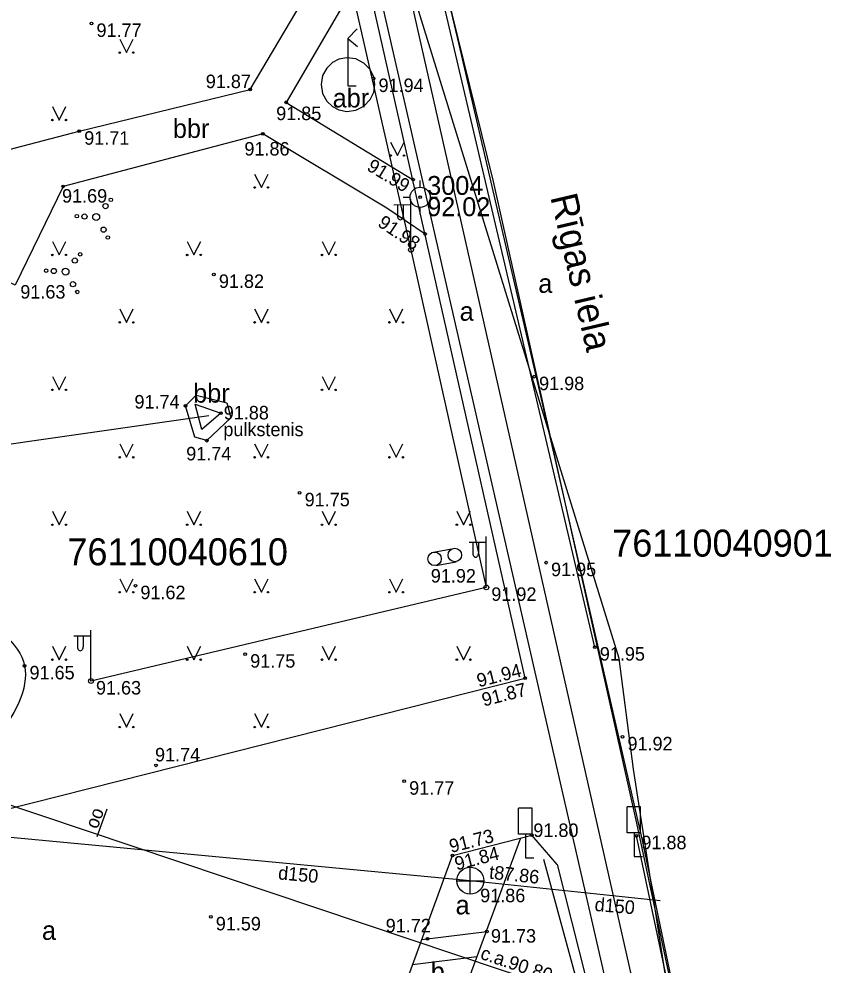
# Model space of a CAD drawing. Extents: x 634272 to 634544, y 247463 to 247653.
# Drawn here: x 634443.51 to 634473.63, y 247553.68 to 247588.75 of the extents above; entities that cross this region are included whole.
import ezdxf

# ---------------------------------------------------------------- set-up
doc = ezdxf.new("R2010")
doc.units = 0
for name, color, linetype in [('APGR_SARK_####_####_#', 7, 'Continuous'), ('APGS_ELEM_####_####_#', 7, 'Continuous'), ('APGS_VADP_ZSPR_####_#', 7, 'Continuous'), ('BUVE_BDET_####_####_#', 7, 'Continuous'), ('BUVE_BDET_####_TKST_#', 7, 'Continuous'), ('BUVE_ELEM_####_####_#', 7, 'Continuous'), ('CELI_CAPM_####_####_#', 7, 'Continuous'), ('CELI_CMAL_####_####_#', 7, 'Continuous'), ('CELI_CSEG_####_TKST_#', 7, 'Continuous'), ('CELI_ELEM_####_####_#', 7, 'Continuous'), ('CELI_IELA_####_TKST_#', 7, 'Continuous'), ('CELI_KAPN_####_####_#', 7, 'Continuous'), ('CELI_SEGL_####_####_#', 7, 'Continuous'), ('CELI_ZIME_####_####_#', 7, 'Continuous'), ('GEOD_ELEM_####_####_#', 7, 'Continuous'), ('GEOD_ELEM_####_TKST_#', 7, 'Continuous'), ('NORB_ZOGS_ZMET_####_#', 7, 'Continuous'), ('RAMI_UZMR_####_####_#', 7, 'Continuous'), ('RELJ_AATZ_####_TKST_#', 7, 'Continuous'), ('RELJ_ELEM_####_####_#', 7, 'Continuous'), ('ROBZ_KADS_####_TKST_#', 7, 'Continuous'), ('ROBZ_PROJ_####_####_#', 7, 'Continuous'), ('SAKK_IZVK_####_TKST_#', 7, 'Continuous'), ('SAKK_KKAN_####_####_#', 7, 'Continuous'), ('SAKK_KKAN_####_TKST_#', 7, 'Continuous'), ('SKAN_ELEM_####_####_#', 7, 'Continuous'), ('SKAN_ELEM_PAST_TKST_#', 7, 'Continuous'), ('SKAN_VADP_PAST_####_#', 7, 'Continuous'), ('SKAN_VADP_PAST_TKST_#', 7, 'Continuous'), ('TERT_DZOG_####_####_#', 7, 'Continuous'), ('TERT_ELEM_####_####_#', 7, 'Continuous'), ('TERT_KONT_####_####_#', 7, 'Continuous')]:
    doc.layers.add(name, color=color, linetype=linetype)

msp = doc.modelspace()

# ---------------------------------------------------------------- linework, layer by layer
at = {"layer": 'APGR_SARK_####_####_#'}
msp.add_line((634472.239, 247522.641), (634452.431, 247609.249), dxfattribs=at)
at = {"layer": 'APGS_ELEM_####_####_#'}
for p, q in [((634458.049, 247580.186), (634458.049, 247582.069)), ((634458.049, 247581.853), (634457.414, 247581.848)), ((634457.549, 247581.849), (634457.549, 247581.457)), ((634457.759, 247581.851), (634457.759, 247581.457)), ((634460.842, 247567.679), (634460.842, 247569.562)), ((634460.842, 247569.346), (634460.207, 247569.341)), ((634460.342, 247569.342), (634460.342, 247568.95)), ((634460.552, 247569.344), (634460.552, 247568.95)), ((634446.181, 247564.209), (634446.181, 247566.092)), ((634446.181, 247565.876), (634445.546, 247565.871)), ((634445.681, 247565.872), (634445.681, 247565.48)), ((634445.891, 247565.874), (634445.891, 247565.48))]:
    msp.add_line(p, q, dxfattribs=at)
for centre in [(634458.049, 247580.186), (634460.842, 247567.679), (634446.181, 247564.209)]:
    msp.add_circle(centre, 0.09, dxfattribs=at)
for centre in [(634457.654, 247581.457), (634460.447, 247568.95), (634445.786, 247565.48)]:
    msp.add_ellipse(centre, major_axis=(0, 0.151), ratio=0.695971, start_param=1.570796, end_param=4.712389, dxfattribs=at)
at = {"layer": 'APGS_VADP_ZSPR_####_#'}
for points in [[(634424.64, 247564.493), (634427.489, 247567.387), (634428.243, 247568.282), (634428.556, 247569.174), (634428.62, 247569.734), (634428.349, 247570.951), (634427.518, 247573.97), (634425.055, 247583.293), (634424.177, 247586.368), (634423.255, 247589.552), (634422.487, 247592.599), (634438.755, 247598.02), (634453.341, 247601.325), (634455.217, 247592.645), (634458.049, 247580.186), (634460.842, 247567.679), (634446.181, 247564.209)], [(634425.999, 247571.336), (634432.246, 247571.428), (634450.555, 247574.05)]]:
    msp.add_lwpolyline(points, dxfattribs=at)
at = {"layer": 'BUVE_BDET_####_####_#'}
msp.add_lwpolyline([(634450.297, 247573.534), (634450.05, 247574.469), (634451.002, 247574.132), (634450.297, 247573.534)], dxfattribs=at)
at = {"layer": 'BUVE_ELEM_####_####_#'}
for centre in [(634459.675, 247568.878), (634458.924, 247568.738)]:
    msp.add_circle(centre, 0.25, dxfattribs=at)
at = {"layer": 'CELI_CAPM_####_####_#'}
for points in [[(634462.278, 247564.311), (634455.906, 247592.579), (634453.174, 247605.031)], [(634386.18, 247584.245), (634386.517, 247583.098), (634389.042, 247573.196), (634391.897, 247562.219), (634393.7, 247555.164), (634394.221, 247554.237), (634394.857, 247553.225), (634395.836, 247552.623), (634399.496, 247551.073), (634400.928, 247550.806), (634417.097, 247555.253), (634426.457, 247557.809), (634427.052, 247555.379), (634437.491, 247558.047), (634462.278, 247564.311)], [(634457.574, 247552.223), (634459.589, 247557.74), (634462.532, 247558.496)], [(634463.467, 247557.413), (634465.341, 247550.039), (634461.38, 247548.991), (634462.172, 247545.409), (634466.133, 247546.478), (634469.47, 247530.921)]]:
    msp.add_lwpolyline(points, dxfattribs=at)
at = {"layer": 'CELI_CMAL_####_####_#'}
for points in [[(634472.031, 247532.571), (634469.381, 247545.11), (634466.419, 247558.939), (634461.107, 247582.724), (634454.551, 247609.343)], [(634454.416, 247599.108), (634444.542, 247596.807), (634437.329, 247582.391), (634445.746, 247584.585), (634452.082, 247586.129), (634455.906, 247592.579)], [(634456.349, 247590.673), (634453.418, 247585.656), (634458.133, 247582.79)], [(634456.705, 247586.313), (634456.666, 247586.587), (634456.535, 247586.869), (634456.303, 247587.111), (634455.998, 247587.265), (634455.672, 247587.306), (634455.377, 247587.25), (634455.138, 247587.127), (634454.929, 247586.928), (634454.773, 247586.647), (634454.715, 247586.313), (634454.773, 247585.978), (634454.929, 247585.697), (634455.138, 247585.499), (634455.377, 247585.376), (634455.672, 247585.319), (634455.998, 247585.361), (634456.303, 247585.514), (634456.535, 247585.757), (634456.666, 247586.039), (634456.705, 247586.313)], [(634458.572, 247580.776), (634457.15, 247581.734), (634452.558, 247584.487), (634445.153, 247582.542), (634443.376, 247578.883), (634438.996, 247580.966), (634436.253, 247580.228), (634434.43, 247576.565)], [(634449.685, 247574.411), (634450.077, 247574.803), (634451.226, 247574.515), (634451.364, 247573.967), (634450.48, 247573.117), (634450.028, 247573.252), (634449.685, 247574.411)], [(634460.04, 247552.762), (634462.126, 247558.392)], [(634463.467, 247557.413), (634462.532, 247558.496)]]:
    msp.add_lwpolyline(points, dxfattribs=at)
at = {"layer": 'CELI_ELEM_####_####_#'}
for p, q in [((634462.538, 247559.497), (634462.038, 247559.497)), ((634462.038, 247558.528), (634462.038, 247559.497)), ((634462.538, 247558.528), (634462.538, 247559.497)), ((634466.566, 247559.551), (634466.066, 247559.551)), ((634466.066, 247558.582), (634466.066, 247559.551)), ((634466.566, 247558.582), (634466.566, 247559.551)), ((634466.566, 247558.582), (634466.066, 247558.582)), ((634466.32, 247558.582), (634466.32, 247557.704)), ((634462.538, 247558.528), (634462.038, 247558.528)), ((634462.292, 247558.528), (634462.292, 247557.65)), ((634462.292, 247557.65), (634462.607, 247557.65)), ((634466.32, 247557.704), (634466.635, 247557.704))]:
    msp.add_line(p, q, dxfattribs=at)
for points in [[(634456.053, 247588.379), (634455.711, 247588.023), (634456.067, 247587.724)], [(634455.711, 247588.023), (634455.711, 247586.271), (634456.01, 247586.271)]]:
    msp.add_lwpolyline(points, dxfattribs=at)
at = {"layer": 'CELI_KAPN_####_####_#'}
msp.add_line((634460.495, 247553.99), (634458.111, 247553.692), dxfattribs=at)
at = {"layer": 'CELI_SEGL_####_####_#'}
msp.add_lwpolyline([(634458.452, 247554.627), (634460.864, 247554.929)], dxfattribs=at)
at = {"layer": 'CELI_ZIME_####_####_#'}
for p, q in [((634458.878, 247568.984), (634459.629, 247569.124)), ((634458.97, 247568.492), (634459.721, 247568.632))]:
    msp.add_line(p, q, dxfattribs=at)
at = {"layer": 'GEOD_ELEM_####_####_#'}
for p, q in [((634458.39, 247582.512), (634458.39, 247582.762)), ((634457.765, 247582.137), (634458.015, 247582.137)), ((634458.765, 247582.137), (634459.015, 247582.137)), ((634458.39, 247581.512), (634458.39, 247581.762))]:
    msp.add_line(p, q, dxfattribs=at)
for radius in [0.375, 0.05]:
    msp.add_circle((634458.39, 247582.137), radius, dxfattribs=at)
at = {"layer": 'NORB_ZOGS_ZMET_####_#'}
for points in [[(634464.866, 247565.466), (634454.698, 247608.782)], [(634471.548, 247534.262), (634466.407, 247558.475)]]:
    msp.add_lwpolyline(points, dxfattribs=at)
at = {"layer": 'RAMI_UZMR_####_####_#'}
msp.add_lwpolyline([(634357.63, 247590.775), (634379.264, 247596.642), (634392.424, 247602.216), (634402.994, 247605.715), (634421.735, 247609.504), (634423.082, 247609.702), (634425.783, 247608.304), (634427.755, 247600.855), (634433.048, 247602.581), (634454.806, 247608.92), (634459.819, 247587.798), (634462.766, 247575.147), (634466.614, 247558.36), (634469.076, 247546.545)], dxfattribs=at)
at = {"layer": 'RELJ_ELEM_####_####_#'}
for centre in [(634446.201, 247588.58), (634456.66, 247586.538), (634452.082, 247586.129), (634453.418, 247585.656), (634445.746, 247584.585), (634452.558, 247584.487), (634458.133, 247582.79), (634445.153, 247582.542), (634458.393, 247582.141), (634458.572, 247580.776), (634450.74, 247579.278), (634462.614, 247575.489), (634449.685, 247574.411), (634451.002, 247574.132), (634450.48, 247573.117), (634453.92, 247571.184), (634463.057, 247568.595), (634447.829, 247567.742), (634451.901, 247565.204), (634464.866, 247565.466), (634443.717, 247564.77), (634462.278, 247564.311), (634465.891, 247562.138), (634448.593, 247561.083), (634457.796, 247560.496), (634462.532, 247558.496), (634466.407, 247558.475), (634459.589, 247557.74), (634450.624, 247555.467), (634458.657, 247554.653), (634460.864, 247554.929)]:
    msp.add_circle(centre, 0.05, dxfattribs=at)
at = {"layer": 'ROBZ_PROJ_####_####_#'}
for points in [[(634465.768, 247565.048), (634453.433, 247604.869)], [(634466.305, 247560.948), (634465.768, 247565.048)], [(634472.285, 247522.369), (634466.305, 247560.948)]]:
    msp.add_lwpolyline(points, dxfattribs=at)
at = {"layer": 'SAKK_IZVK_####_TKST_#'}
msp.add_line((634446.414, 247558.452), (634446.786, 247559.47), dxfattribs=at)
at = {"layer": 'SAKK_KKAN_####_####_#'}
for points in [[(634452.888, 247611.435), (634454.857, 247603.576), (634466.565, 247551.758), (634472.201, 247519.993)], [(634466.565, 247551.758), (634428.878, 247564.406)]]:
    msp.add_lwpolyline(points, dxfattribs=at)
at = {"layer": 'SKAN_ELEM_####_####_#'}
for p, q in [((634460.247, 247556.307), (634460.247, 247557.307)), ((634459.747, 247556.807), (634460.747, 247556.807))]:
    msp.add_line(p, q, dxfattribs=at)
msp.add_circle((634460.247, 247556.807), 0.5, dxfattribs=at)
at = {"layer": 'SKAN_VADP_PAST_####_#'}
msp.add_lwpolyline([(634467.293, 247556.065), (634460.247, 247556.807), (634435.579, 247559.128), (634432.448, 247572.232), (634426.846, 247593.259), (634423.583, 247606.965), (634413.214, 247604.726), (634403.305, 247602.476), (634405.576, 247593.489), (634409.131, 247581.899)], dxfattribs=at)
at = {"layer": 'TERT_DZOG_####_####_#'}
msp.add_lwpolyline([(634464.963, 247550.289), (634462.971, 247557.593)], dxfattribs=at)
at = {"layer": 'TERT_ELEM_####_####_#'}
for p, q in [((634447.25, 247588), (634447.5, 247587.5)), ((634447.5, 247587.5), (634447.75, 247588)), ((634444.75, 247585.5), (634445, 247585)), ((634445, 247585), (634445.25, 247585.5)), ((634457.294, 247584.185), (634457.544, 247583.685)), ((634457.544, 247583.685), (634457.794, 247584.185)), ((634452.25, 247583), (634452.5, 247582.5)), ((634452.5, 247582.5), (634452.75, 247583)), ((634444.75, 247580.5), (634445, 247580)), ((634445, 247580), (634445.25, 247580.5)), ((634449.75, 247580.5), (634450, 247580)), ((634450, 247580), (634450.25, 247580.5)), ((634454.75, 247580.5), (634455, 247580)), ((634455, 247580), (634455.25, 247580.5)), ((634447.25, 247578), (634447.5, 247577.5)), ((634447.5, 247577.5), (634447.75, 247578)), ((634452.25, 247578), (634452.5, 247577.5)), ((634452.5, 247577.5), (634452.75, 247578)), ((634457.25, 247578), (634457.5, 247577.5)), ((634457.5, 247577.5), (634457.75, 247578)), ((634444.75, 247575.5), (634445, 247575)), ((634445, 247575), (634445.25, 247575.5)), ((634454.75, 247575.5), (634455, 247575)), ((634455, 247575), (634455.25, 247575.5)), ((634447.25, 247573), (634447.5, 247572.5)), ((634447.5, 247572.5), (634447.75, 247573)), ((634452.25, 247573), (634452.5, 247572.5)), ((634452.5, 247572.5), (634452.75, 247573)), ((634457.25, 247573), (634457.5, 247572.5)), ((634457.5, 247572.5), (634457.75, 247573)), ((634444.75, 247570.5), (634445, 247570)), ((634445, 247570), (634445.25, 247570.5)), ((634449.75, 247570.5), (634450, 247570)), ((634450, 247570), (634450.25, 247570.5)), ((634454.75, 247570.5), (634455, 247570)), ((634455, 247570), (634455.25, 247570.5)), ((634459.75, 247570.5), (634460, 247570)), ((634460, 247570), (634460.25, 247570.5)), ((634447.25, 247568), (634447.5, 247567.5)), ((634447.5, 247567.5), (634447.75, 247568)), ((634452.25, 247568), (634452.5, 247567.5)), ((634452.5, 247567.5), (634452.75, 247568)), ((634457.25, 247568), (634457.5, 247567.5)), ((634457.5, 247567.5), (634457.75, 247568)), ((634444.75, 247565.5), (634445, 247565)), ((634445, 247565), (634445.25, 247565.5)), ((634449.75, 247565.5), (634450, 247565)), ((634450, 247565), (634450.25, 247565.5)), ((634454.75, 247565.5), (634455, 247565)), ((634455, 247565), (634455.25, 247565.5)), ((634459.75, 247565.5), (634460, 247565)), ((634460, 247565), (634460.25, 247565.5)), ((634447.25, 247563), (634447.5, 247562.5)), ((634447.5, 247562.5), (634447.75, 247563)), ((634452.25, 247563), (634452.5, 247562.5)), ((634452.5, 247562.5), (634452.75, 247563))]:
    msp.add_line(p, q, dxfattribs=at)
for centre, radius in [((634447.25, 247587.5), 0.028), ((634447.75, 247587.5), 0.0263), ((634444.75, 247585), 0.028), ((634445.25, 247585), 0.0263), ((634457.293, 247583.685), 0.028), ((634457.793, 247583.685), 0.0263), ((634452.25, 247582.5), 0.028), ((634452.75, 247582.5), 0.0263), ((634446.918, 247582.042), 0.064), ((634446.722, 247581.811), 0.096), ((634445.656, 247581.437), 0.064), ((634445.94, 247581.424), 0.096), ((634446.374, 247581.403), 0.128), ((634446.65, 247580.936), 0.096), ((634446.808, 247580.647), 0.064), ((634444.75, 247580), 0.028), ((634445.25, 247580), 0.0263), ((634445.782, 247580.022), 0.064), ((634449.75, 247580), 0.028), ((634450.25, 247580), 0.0263), ((634454.75, 247580), 0.028), ((634455.25, 247580), 0.0263), ((634445.586, 247579.791), 0.096), ((634444.52, 247579.417), 0.064), ((634444.804, 247579.404), 0.096), ((634445.238, 247579.383), 0.128), ((634445.514, 247578.916), 0.096), ((634445.672, 247578.627), 0.064), ((634447.25, 247577.5), 0.028), ((634447.75, 247577.5), 0.0263), ((634452.25, 247577.5), 0.028), ((634452.75, 247577.5), 0.0263), ((634457.25, 247577.5), 0.028), ((634457.75, 247577.5), 0.0263), ((634444.75, 247575), 0.028), ((634445.25, 247575), 0.0263), ((634454.75, 247575), 0.028), ((634455.25, 247575), 0.0263), ((634447.25, 247572.5), 0.028), ((634447.75, 247572.5), 0.0263), ((634452.25, 247572.5), 0.028), ((634452.75, 247572.5), 0.0263), ((634457.25, 247572.5), 0.028), ((634457.75, 247572.5), 0.0263), ((634444.75, 247570), 0.028), ((634445.25, 247570), 0.0263), ((634449.75, 247570), 0.028), ((634450.25, 247570), 0.0263), ((634454.75, 247570), 0.028), ((634455.25, 247570), 0.0263), ((634459.75, 247570), 0.028), ((634460.25, 247570), 0.0263), ((634447.25, 247567.5), 0.028), ((634447.75, 247567.5), 0.0263), ((634452.25, 247567.5), 0.028), ((634452.75, 247567.5), 0.0263), ((634457.25, 247567.5), 0.028), ((634457.75, 247567.5), 0.0263), ((634444.75, 247565), 0.028), ((634445.25, 247565), 0.0263), ((634449.75, 247565), 0.028), ((634450.25, 247565), 0.0263), ((634454.75, 247565), 0.028), ((634455.25, 247565), 0.0263), ((634459.75, 247565), 0.028), ((634460.25, 247565), 0.0263), ((634447.25, 247562.5), 0.028), ((634447.75, 247562.5), 0.0263), ((634452.25, 247562.5), 0.028), ((634452.75, 247562.5), 0.0263)]:
    msp.add_circle(centre, radius, dxfattribs=at)
at = {"layer": 'TERT_KONT_####_####_#'}
msp.add_spline([(634436.545, 247568.569), (634443.717, 247564.77), (634439.253, 247558.492)], degree=3, dxfattribs=at)

# ---------------------------------------------------------------- texts
at = {"layer": 'BUVE_BDET_####_TKST_#'}
msp.add_text('pulkstenis', height=0.5, dxfattribs=at).set_placement((634451.091, 247573.284))
at = {"layer": 'CELI_CSEG_####_TKST_#'}
for s, p in [('abr', (634455.146, 247585.467)), ('bbr', (634449.22, 247584.337)), ('a', (634462.771, 247578.596)), ('a', (634459.855, 247577.562)), ('bbr', (634449.972, 247574.526)), ('a', (634459.703, 247555.56)), ('a', (634444.365, 247554.615)), ('b', (634458.783, 247553.087))]:
    msp.add_text(s, height=0.7, dxfattribs=at).set_placement(p)
at = {"layer": 'CELI_IELA_####_TKST_#'}
msp.add_text('Rīgas iela', height=1, rotation=283.2104, dxfattribs=at).set_placement((634463.21, 247582.152))
at = {"layer": 'GEOD_ELEM_####_TKST_#'}
for s, p in [(' 3004', (634458.39, 247582.226)), (' 92.02', (634458.39, 247581.437))]:
    msp.add_text(s, height=0.7, dxfattribs=at).set_placement(p)
at = {"layer": 'RELJ_AATZ_####_TKST_#'}
for s, p in [(' 91.77', (634446.201, 247588.08)), (' 91.87', (634450.254, 247586.183)), (' 91.94', (634456.66, 247586.038)), (' 91.85', (634452.865, 247584.997)), (' 91.71', (634445.746, 247584.085)), (' 91.86', (634451.686, 247583.685)), (' 91.69', (634444.923, 247581.94)), (' 91.82', (634450.74, 247578.778)), (' 91.63', (634443.376, 247578.383)), (' 91.98', (634462.614, 247574.989)), (' 91.74', (634447.609, 247574.309)), (' 91.88', (634450.92, 247573.904)), (' 91.74', (634449.528, 247572.386)), (' 91.75', (634453.92, 247570.684)), (' 91.92', (634458.598, 247567.859)), (' 91.95', (634463.057, 247568.095)), (' 91.62', (634447.829, 247567.242)), (' 91.92', (634460.842, 247567.179)), (' 91.75', (634451.901, 247564.704)), (' 91.95', (634464.866, 247564.966)), (' 91.65', (634443.717, 247564.27)), (' 91.63', (634446.181, 247563.709)), (' 91.92', (634465.891, 247561.638)), (' 91.74', (634448.372, 247561.23)), (' 91.77', (634457.796, 247559.996)), (' 91.80', (634462.401, 247558.429)), (' 91.88', (634466.407, 247557.975)), (' 91.59', (634450.624, 247554.967)), (' 91.72', (634456.925, 247554.894)), (' 91.73', (634460.828, 247554.513))]:
    msp.add_text(s, height=0.5, dxfattribs=at).set_placement(p)
for s, rotation, p in [(' 91.99', 328.7068, (634456.219, 247583.262)), (' 91.98', 326.0319, (634456.624, 247581.197)), (' 91.94', 14.1825, (634460.381, 247563.927)), (' 91.87', 14.1825, (634460.568, 247563.217)), (' 91.73', 14.4067, (634459.359, 247557.787)), (' 91.84', 14.4067, (634459.56, 247557.141))]:
    msp.add_text(s, height=0.5, rotation=rotation, dxfattribs=at).set_placement(p)
at = {"layer": 'ROBZ_KADS_####_TKST_#'}
for s, p in [('76110040901', (634465.512, 247568.818)), ('76110040610', (634445.306, 247568.498))]:
    msp.add_text(s, height=1, dxfattribs=at).set_placement(p)
at = {"layer": 'SAKK_IZVK_####_TKST_#'}
msp.add_text('oo', height=0.5, rotation=69.9407, dxfattribs=at).set_placement((634446.42, 247558.699))
at = {"layer": 'SAKK_KKAN_####_TKST_#'}
msp.add_text('c.a.90.80', height=0.5, rotation=341.4479, dxfattribs=at).set_placement((634460.59, 247553.921))
at = {"layer": 'SKAN_ELEM_PAST_TKST_#'}
msp.add_text(' 91.86', height=0.5, dxfattribs=at).set_placement((634460.429, 247556.011))
at = {"layer": 'SKAN_VADP_PAST_TKST_#'}
for s, rotation, p in [('d150', 354.6249, (634453.106, 247556.861)), ('t87.86', 353.9899, (634460.93, 247556.886)), ('d150', 355.1932, (634464.846, 247555.688))]:
    msp.add_text(s, height=0.5, rotation=rotation, dxfattribs=at).set_placement(p)

doc.saveas('drawing.dxf')
